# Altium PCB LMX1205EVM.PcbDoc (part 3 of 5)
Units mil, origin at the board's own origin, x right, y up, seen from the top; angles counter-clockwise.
Board outline 5000 x 5000 mil, 6 copper layers (Top Layer, RF GND, Signal Layer 3, Signal Layer 4, Signal Layer 5, Bottom Layer), stack 61.6 mil thick; 176 components, 99 nets, 572 pads, 2473 vias.
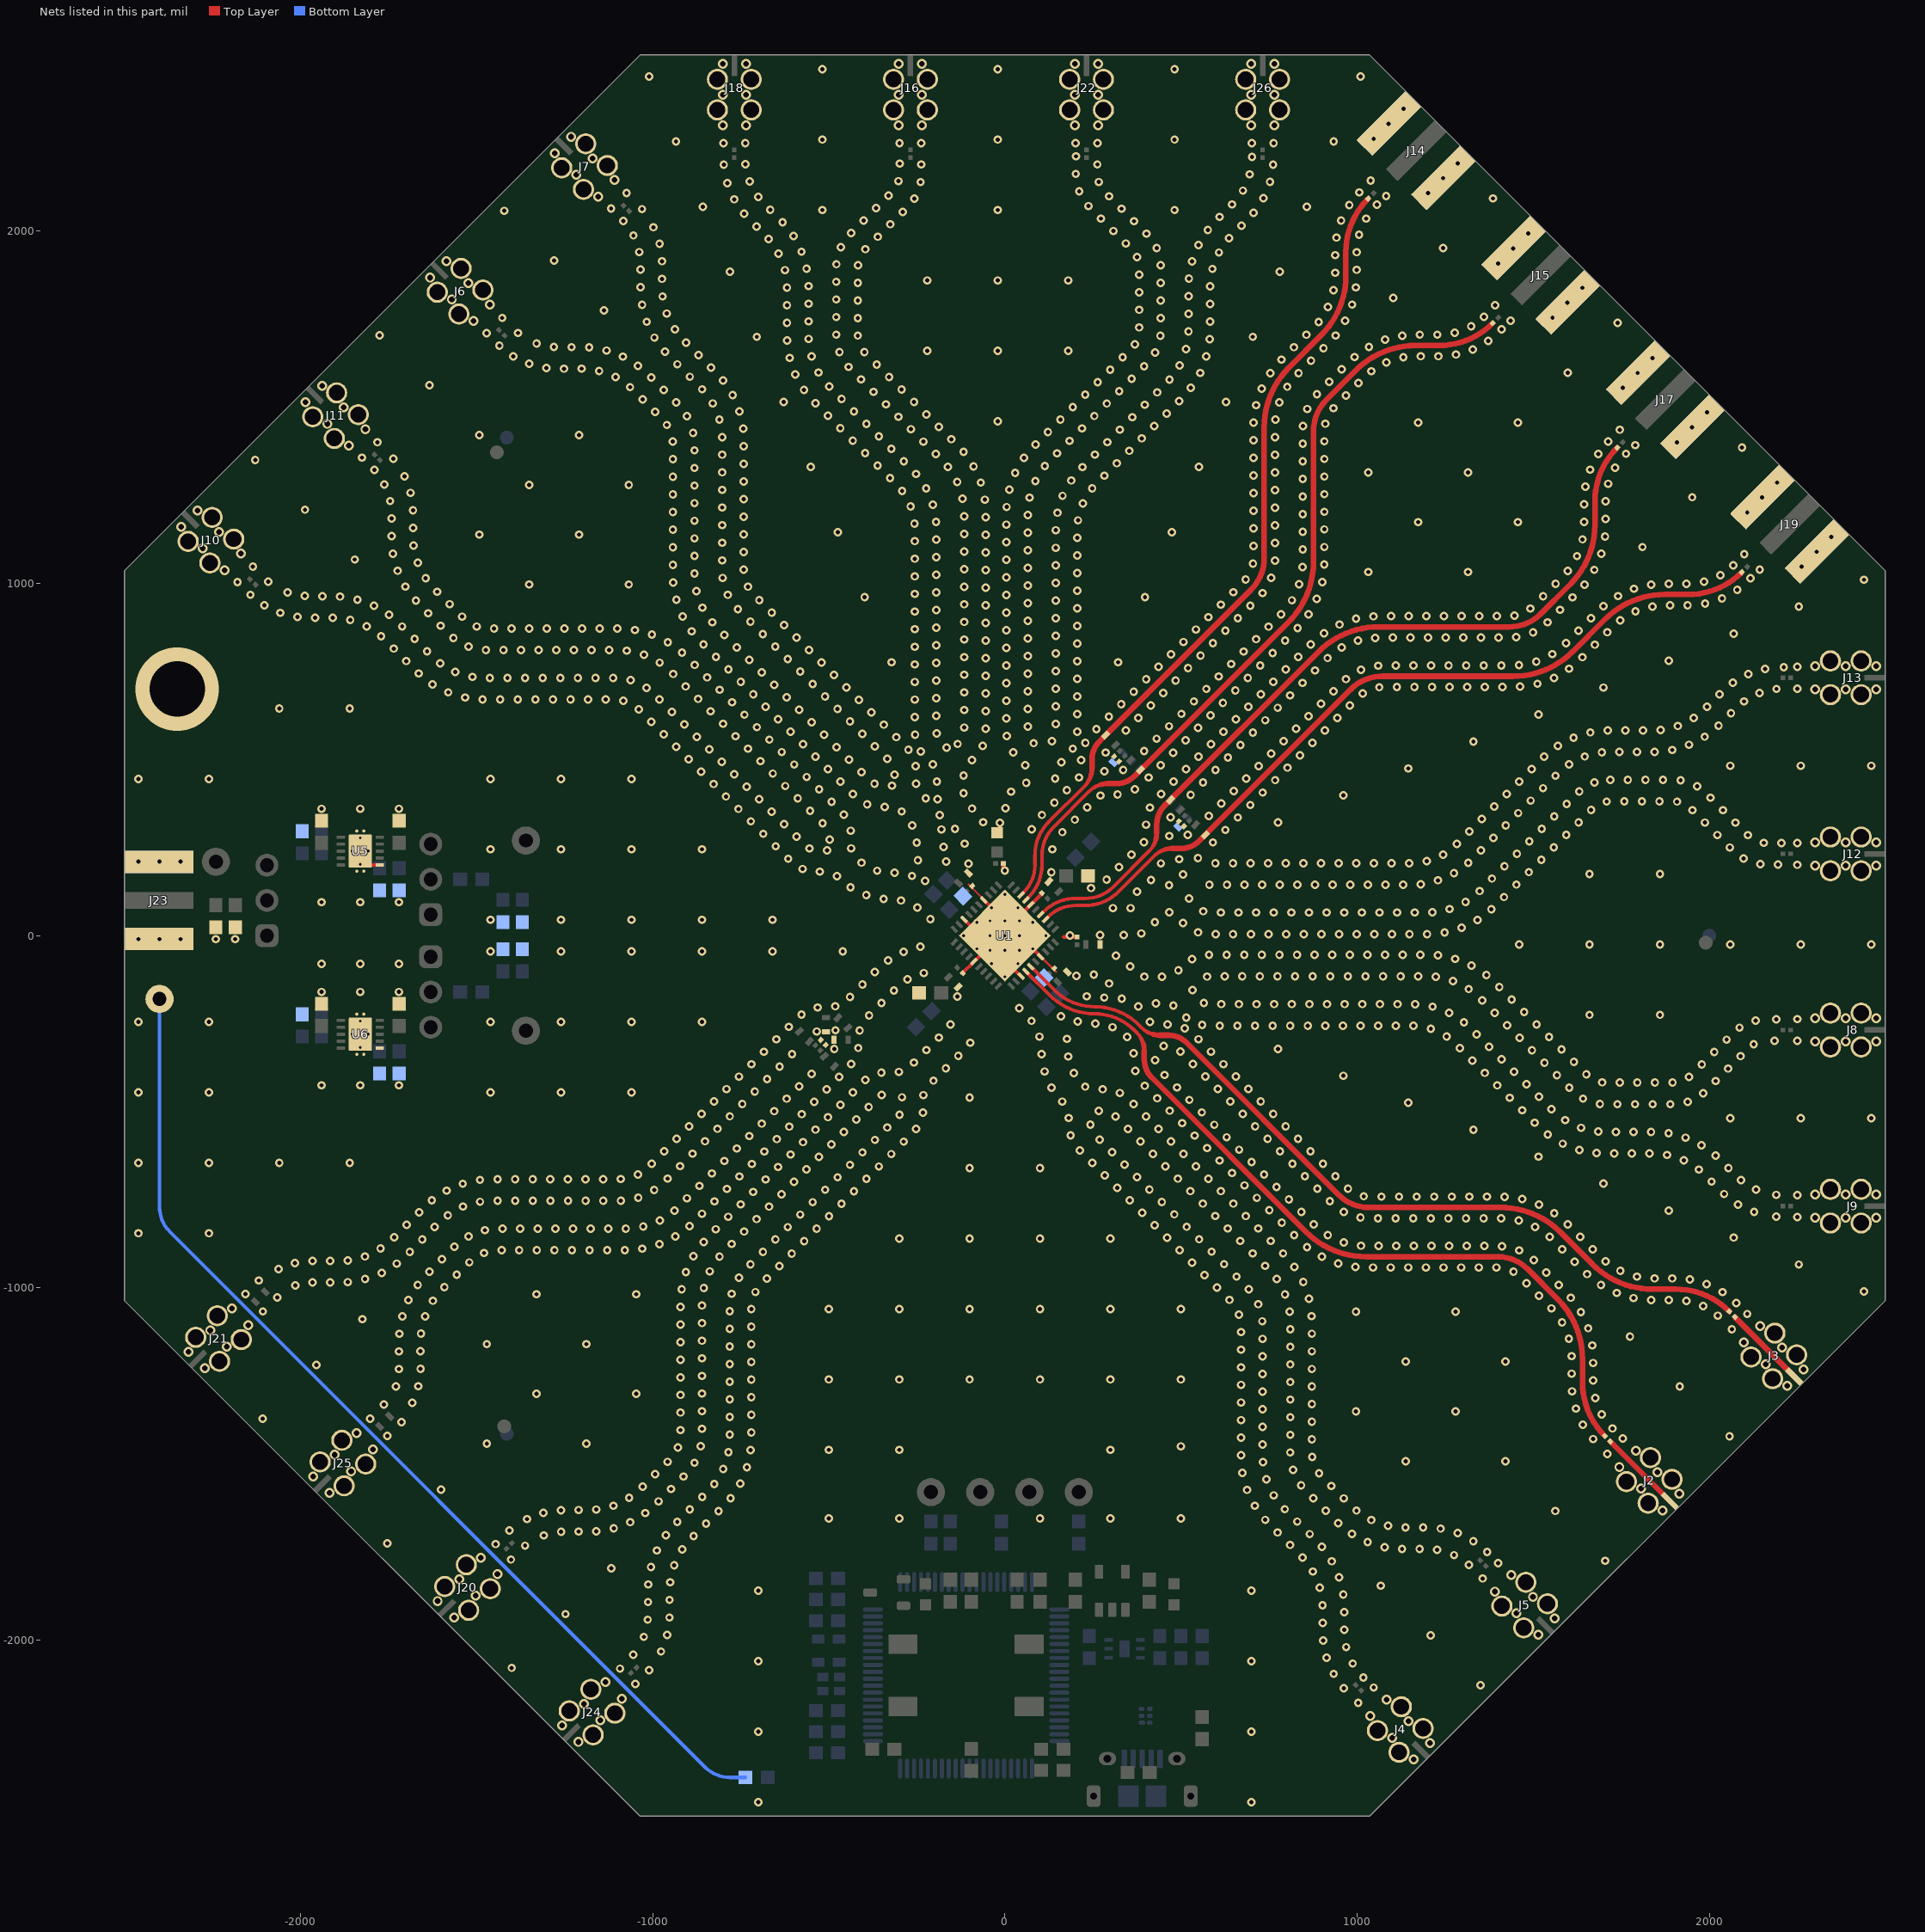
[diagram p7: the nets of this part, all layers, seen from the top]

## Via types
v1: diameter 24, hole 12, Top Layer to Bottom Layer, tented both sides, 2320 vias
v2: diameter 28, hole 16, Top Layer to Bottom Layer, 120 vias
v3: diameter 19.68, hole 7.87, Top Layer to Bottom Layer, tented both sides, 29 vias
v4: diameter 24, hole 12, Top Layer to Bottom Layer, tented bottom, 3 vias
v5: diameter 236.22, hole 157.48, Top Layer to Bottom Layer, tented both sides, 1 vias

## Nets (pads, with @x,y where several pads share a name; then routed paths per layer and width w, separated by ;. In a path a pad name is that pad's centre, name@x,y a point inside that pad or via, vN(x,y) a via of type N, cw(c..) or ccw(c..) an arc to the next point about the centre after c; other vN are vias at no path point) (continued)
GND: C3.2 C4.2 C5.2 C6.2 C8.2 C9.2 C10.2 C11.2 C12.2 C13.2 C14.2 C15.2 C16.1 C21.1 C35.2 C36.2 C51.2 C52.2 C53.1 C54.2 C55.2 C56.2 C57.1 C58.1 C59.2 C60.2 C61.2 C62.1 C63.2 C64.2 C65.1 C66.1 C68.1 C69.1 C70.1 C71.1 J2.2 J2.3 J2.4 J2.5 J3.2 J3.3 J3.4 J3.5 J4.2 J4.3 J4.4 J4.5 J5.2 J5.3 J5.4 J5.5 J6.2 J6.3 J6.4 J6.5 J7.2 J7.3 J7.4 J7.5 J8.2 J8.3 J8.4 J8.5 J9.2 J9.3 J9.4 J9.5 J10.2 J10.3 J10.4 J10.5 J11.2 J11.3 J11.4 J11.5 J12.2 J12.3 J12.4 J12.5 J13.2 J13.3 J13.4 J13.5 J14.2 J14.3 J14.4 J14.5 J15.2 J15.3 J15.4 J15.5 J16.2 J16.3 J16.4 J16.5 J17.2 J17.3 J17.4 J17.5 J18.2 J18.3 J18.4 J18.5 J19.2 J19.3 J19.4 J19.5 J20.2 J20.3 J20.4 J20.5 J21.2 J21.3 J21.4 J21.5 J22.2 J22.3 J22.4 J22.5 J23.2 J23.3 J23.4 J23.5 J24.2 J24.3 J24.4 J24.5 J25.2 J25.3 J25.4 J25.5 J26.2 J26.3 J26.4 J26.5 R5.1 R11.1 R24.2 R28.1 R40.1 R43.1 R44.1 TP3.1 U1.5 U1.13 U1.17 U1.26 U1.34 U1.38 U1.41 U5.6 U5.11 U6.6 U6.11 | length 4042.9
  Top Layer w6: -102.53,144.96 U1.34@-62.23,104.65 ; U1.17@104.65,-62.23 144.96,-102.53
  Top Layer w9.45: U5.11@-1830,200.63 U5.6@-1774.88,200.63
  Top Layer w9.84: U1.38@-115.53,45.93 U1.41@-69.6,0 ; U1.34@-59.85,101.61 v3(-37.58,79.34) ; U1.41@-41.76,-27.84 v3(-41.76,0)
  Top Layer w10: U5.11@-1830,200.63 U5.11@-1830,240 ; C10.2@-120.1,-106.18 U1.5@-87.69,-73.77 U1.41@-41.76,-27.84 ; U1.41@-69.6,0 v3(-41.76,0) v3(0,0) ; v3(-37.58,79.34) v3(0,41.76) U1.41@0,13.92 ; C4.2@-22,292.56 -14,300.56 v1(-14,320) ; U1.13@45.93,-115.53 0,-69.6 v3(0,-41.76) v3(0,0) ; U1.17@101.61,-59.85 v3(79.34,-37.58) v3(41.76,0) v3(0,0) ; C8.2@106.18,120.1 U1.26@73.77,87.69 U1.41@0,13.92 ; v3(0,0) U1.41@0,13.92
  Top Layer w12: v1@-3.98,190 C3.2@-3.98,205 ; 167.42,-3.98 C5.2@205,-3.98
  Bottom Layer w10: TP3.1@-2400,-180 -2400,-770.26 ccw(c-2300,-770.26) -2370.71,-840.97 -850.97,-2360.71 ccw(c-780.26,-2290) -780.26,-2390 R24.2@-736.5,-2390
  other v1: -700,-2460 700,-2460 -700,-2260 700,-2260 1003.38,-2178.6 962.81,-2136.42 1047.23,-2134.76 1350.57,-2128.39 -1048.64,-2124.86 1017.96,-2106.24 933.65,-2095.81 -1010,-2085.26 -1092.48,-2081.02 -1400.07,-2078.89 987.62,-2066.5 -700,-2060 700,-2060 913.99,-2049.83 -1055,-2041.7 -976.26,-2032.34 969.12,-2020.05 903.66,-2000.91 -1025.06,-1990.82 1209.15,-1986.97 -959.01,-1985.41 963.55,-1970.36 902.38,-1950.93 -1014.04,-1942.05 -952.14,-1935.88 -1247.34,-1926.16 963.55,-1920.36 901.94,-1900.93 -1013.05,-1892.06 -951.87,-1885.89 960.69,-1870.44 -700,-1860 700,-1860 894.18,-1851.54 1067.73,-1845.55 -1012.33,-1842.06 -950.42,-1835.91 1356.94,-1825.04 949.21,-1821.77 874.89,-1805.41 -1117.23,-1796.05 -1004.58,-1792.67 -938.68,-1787.31 1317.36,-1786.07 1400.78,-1781.2 928.49,-1776.27 1704.13,-1774.84 -1402.19,-1771.3 844.93,-1765.38 1275.4,-1758.88 1369.55,-1750.22 -987.89,-1745.54 1227.65,-1744.04 -915.83,-1742.83 1127.72,-1741.43 1177.72,-1741.37 1078.01,-1736.02 900.09,-1735.12 -1362,-1732 809.76,-1729.83 -1446.03,-1727.46 -1753.62,-1725.34 1030.15,-1721.57 1330.28,-1719.27 -883.56,-1704.64 -1308.69,-1702.76 -962.49,-1702.47 865.48,-1699.03 985.57,-1698.92 1285.77,-1696.48 774.41,-1694.48 -1259.73,-1692.63 -1209.73,-1691.87 -1159.74,-1690.96 -1406.44,-1689 1237.5,-1683.44 -1110.47,-1682.43 1137.61,-1680.19 1187.61,-1680.19 1087.85,-1675.29 -848.21,-1669.28 946.25,-1668.03 -1063.55,-1665.16 -929.95,-1664.51 830.12,-1663.68 739.46,-1658.72 1040.54,-1659.1 -1356.45,-1656.53 -500,-1655 -300,-1655 100,-1655 300,-1655 500,-1655 -1309.79,-1638.57 -1020.77,-1639.28 -812.85,-1633.93 910.75,-1632.83 1562.71,-1633.42 998.38,-1632.23 -1260.34,-1631.18 -1210.34,-1630.7 -1160.36,-1629.46 -894.59,-1629.15 794.77,-1628.32 -1111.56,-1618.54 709.55,-1618.65 -983.2,-1606.29 962.18,-1597.74 -778.7,-1597.41 875.39,-1597.47 -1066.71,-1596.45 -859.24,-1593.8 763.61,-1589.22 687.76,-1573.65 -1600.89,-1572.61 -947.84,-1570.93 -1028.11,-1564.68 926.82,-1562.39 841.15,-1561.04 -825.04,-1557.32 -751.48,-1555.47 742.48,-1543.9 -912.49,-1535.57 -992.75,-1529.32 892.15,-1526.36 674.71,-1525.38 818.26,-1516.59 -799.53,-1514.32 -732.26,-1509.31 -881.09,-1496.66 732.6,-1494.89 -957.39,-1493.96 1138.44,-1492 1421.28,-1492 872.68,-1480.31 670.45,-1475.56 1710.49,-1471.49 -784.85,-1466.52 810.26,-1467.23 -721.6,-1460.46 -500,-1460 -300,-1460 300,-1460 -928.15,-1453.41 -863.23,-1449.96 500,-1450 731.63,-1444.9 -1470.78,-1442.5 -1187.94,-1442.5 871.63,-1430.32 1669.91,-1429.32 1754.33,-1427.65 670.45,-1425.56 -1752.92,-1420.58 2057.68,-1421.28 -781.13,-1416.66 810.45,-1417.23 -719.95,-1410.48 -921.13,-1403.91 -859.95,-1400.07 1725.06,-1399.14 731.63,-1394.9 1640.76,-1388.7 -1713,-1381 871.63,-1380.32 670.45,-1375.56 -2107.18,-1371.79 -1802.42,-1371.08 -781.13,-1366.66 810.45,-1367.23 -719.95,-1360.48 1694.72,-1359.4 -921.13,-1353.91 997.02,-1350.57 1279.86,-1350.57 -859.95,-1350.07 731.63,-1344.9 1621.1,-1342.72 -1763,-1331 871.63,-1330.32 -1682.1,-1326.43 670.45,-1325.56 -781.13,-1316.66 810.45,-1317.23 1676.23,-1312.94 -719.95,-1310.48 -921.13,-1303.91 -1329.36,-1301.08 -1046.52,-1301.08 -859.95,-1300.07 731.63,-1294.9 1610.77,-1293.8 -1729.04,-1279.68 871.63,-1280.32 1916.26,-1279.86 -1665.04,-1279.43 670.45,-1275.56 -781.13,-1266.66 810.45,-1267.23 1670.66,-1263.25 -719.95,-1260.48 -500,-1260 -300,-1260 -100,-1260 100,-1260 300,-1260 500,-1260 -921.13,-1253.91 -859.95,-1250.07 731.63,-1244.9 1609.48,-1243.82 -1720.33,-1230.45 -1658.79,-1229.82 871.63,-1230.32 670.45,-1225.56 -1954.44,-1219.05 -781.13,-1216.66 810.45,-1217.23 1670.66,-1213.25 -719.95,-1210.48 1138.44,-1209.15 1421.28,-1209.15 -921.13,-1203.91 -859.95,-1200.07 731.63,-1194.9 1609.05,-1193.82 -1720.16,-1180.45 -1658.98,-1179.82 871.63,-1180.32 670.45,-1175.56 -781.13,-1166.66 810.45,-1167.23 1667.79,-1163.34 -1470.78,-1159.66 -1187.94,-1159.66 -719.95,-1160.48 -921.13,-1153.91 -859.95,-1150.07 731.63,-1144.9 1601.29,-1144.43 1774.84,-1138.44 -1719.18,-1130.46 -1657.6,-1129.84 871.63,-1130.32 670.45,-1125.56 2064.04,-1117.94 -781.13,-1116.66 810.45,-1117.23 1656.32,-1114.67 -719.95,-1110.48 -921.13,-1103.91 -859.95,-1100.07 1582,-1098.3 730.96,-1094.9 -1824.34,-1088.94 -1710.44,-1081.23 -1646.11,-1081.17 871.02,-1080.32 2024.49,-1078.98 664.96,-1075.87 2107.89,-1074.1 1635.6,-1069.17 997.02,-1067.73 1279.86,-1067.73 -2106.47,-1067.02 -781.13,-1066.66 808.49,-1067.27 -719.95,-1060.48 -500,-1060 -300,-1060 -100,-1060 100,-1060 300,-1060 500,-1060 1552.03,-1058.27 -921.13,-1053.91 1982.53,-1051.79 -859.95,-1050.07 719.14,-1046.32 2076.62,-1043.08 -1623.5,-1036.58 1934.79,-1036.94 -1693.11,-1034.33 637.36,-1034.17 1834.86,-1034.33 1884.86,-1034.26 863.7,-1030.86 1785.15,-1028.92 1607.2,-1028.01 -2066,-1027 1516.87,-1022.73 795.66,-1018.94 -2155.97,-1017.53 -1329.36,-1018.23 -1046.52,-1018.23 -775.58,-1016.97 1737.29,-1014.47 -708.05,-1011.92 2037.34,-1012.13 2439.04,-1010.28 -917.63,-1004.03 692.76,-1003.84 -854.52,-1000.37 602.01,-998.82 -1591.39,-998.25 -2014.65,-993.51 -1667,-991.69 1572.59,-991.93 1692.71,-991.83 1992.83,-989.36 1481.51,-987.37 -1965.4,-984.91 -1915.4,-984.77 -1865.41,-983.77 847.21,-983.66 -2118,-979 1944.56,-976.32 -1816.19,-974.93 771.68,-975.07 -675.85,-973.67 1844.67,-973.09 1894.67,-973.09 -755.15,-971.33 657.8,-968.1 1794.91,-968.17 -1556.04,-962.9 566.65,-963.46 1653.38,-960.95 -1769.3,-957.58 1537.23,-956.57 -905.55,-955.51 -1633.88,-954.23 1444.01,-954.3 -837.67,-953.29 1747.61,-951.97 -2062.23,-946.91 1045.46,-942.34 1095.46,-942.34 1145.46,-942.34 1195.46,-942.34 1245.46,-942.34 1295.46,-942.34 1345.46,-942.34 1395.46,-942.34 995.49,-940.78 822.19,-940.37 -640.5,-938.31 738.68,-937.5 -722.32,-933.62 2254.27,-933.75 622.45,-932.74 -1726.73,-931.36 -2015.27,-929.74 946.56,-930.49 -1520.6,-927.62 531.3,-928.11 1617.88,-925.74 1705.45,-925.09 -1915.67,-923.59 -1965.67,-923.43 -1865.69,-922.23 1501.85,-921.24 -1598.53,-918.87 -810.21,-911.51 900.26,-911.62 -1817,-910.87 -884.23,-910.28 -605.14,-902.96 703.33,-902.15 789.89,-902.2 -1478.27,-901.01 -1689.32,-898.19 -686.96,-898.26 587.09,-897.39 1460.11,-893.73 -1428.94,-892.84 -1378.94,-892.84 -1328.94,-892.84 -1278.94,-892.84 -1228.94,-892.84 -1178.94,-892.84 -1128.94,-892.84 -1078.94,-892.84 495.94,-892.75 1669.25,-890.6 1582.52,-890.39 -1029.11,-888.8 -1772.35,-888.36 858.12,-884.71 -1563.2,-883.49 1411.57,-881.7 1061.58,-881.16 1111.58,-881.16 1161.58,-881.16 1211.58,-881.16 1261.58,-881.16 1311.58,-881.16 1361.58,-881.16 1011.58,-880.37 -980.77,-876.02 -775.6,-875.43 962.43,-871.19 -855.14,-869.62 -569.79,-867.6 667.97,-866.79 754.54,-866.84 -1653.96,-862.83 -651.61,-862.91 551.74,-862.03 -300,-860 -100,-860 100,-860 300,-860 460.58,-857.4 2069.49,-857.21 -1733.96,-856.32 1546.68,-855.53 1633.89,-855.24 -1522.84,-853.98 -935.7,-854.36 821.52,-850.64 916.82,-850.71 -2460,-845 -2260,-845 -740.24,-840.07 -1476.03,-836.38 -820.37,-833.68 -1426.26,-831.67 -1376.26,-831.67 -1326.26,-831.67 -1276.26,-831.67 -1226.26,-831.67 -1176.26,-831.67 -1126.26,-831.67 -1076.26,-831.67 -534.43,-832.25 632.62,-831.44 719.18,-831.49 -616.25,-827.55 -1618.6,-827.48 516.38,-826.68 1505.66,-826.94 -1026.6,-825.83 -895.47,-824.67 425.23,-822.04 -1698.61,-820.97 877.35,-820.01 1598.63,-819.8 786.17,-815.28 1459.07,-808.8 -979.71,-808.47 -704.89,-804.71 1059.49,-802.34 1109.49,-802.34 1159.49,-802.34 1209.49,-802.34 1259.49,-802.34 1309.49,-802.34 1359.49,-802.34 1409.49,-802.35 1009.52,-800.46 2250,-799 -785.02,-798.33 2190,-797.5 -499.08,-796.89 597.26,-796.08 683.83,-796.13 -1581.57,-793.89 -580.9,-792.2 481.02,-791.32 -859.66,-789.78 1559.92,-788.15 389.87,-786.68 -1663.25,-785.61 842.03,-784.63 962.12,-784.54 2127.35,-784.75 -938.23,-780.56 1884.71,-780.67 750.81,-779.93 -1538.17,-769.06 -669.53,-769.36 1516.16,-763.95 2081.98,-763.74 -749.66,-762.97 -463.72,-761.54 561.91,-760.73 648.47,-760.78 -545.54,-756.84 -1490.01,-755.61 445.67,-755.97 -824.3,-754.42 922.68,-753.81 -1440.09,-752.84 -1390.09,-752.84 -1340.09,-752.84 -1290.09,-752.84 -1240.09,-752.84 -1190.09,-752.84 -1140.09,-752.84 -1090.09,-752.58 -1626.92,-751.26 354.52,-751.33 806.67,-749.27 1468.78,-748 -902.24,-745.84 715.46,-744.57 -1040.86,-743.8 1419.2,-741.54 1069.2,-741.16 1119.2,-741.16 1169.2,-741.16 1219.2,-741.16 1269.2,-741.16 1319.2,-741.16 1369.2,-741.16 1019.21,-740.02 2250,-737 2190,-736 -634.18,-734 2042.1,-733.58 -714.31,-727.62 -428.37,-726.18 526.55,-725.37 613.12,-725.42 -1585.06,-723.92 -995.76,-722.21 -510.19,-721.49 410.31,-720.61 2132.61,-720.93 -788.95,-719.07 887.33,-718.45 974.21,-718.24 319.16,-715.97 771.32,-713.92 -866.88,-710.49 680.1,-709.22 -1539.03,-704.39 1699.94,-704.14 -598.82,-698.65 2006.56,-698.41 -1490.22,-693.55 2090.32,-694.25 -1440.25,-691.67 -1390.25,-691.67 -1340.25,-691.67 -1290.25,-691.67 -1240.25,-691.67 -1190.25,-691.67 -1140.25,-691.67 -678.95,-692.26 -1090.26,-691.12 -393.01,-690.83 -957.68,-689.81 491.2,-690.02 577.76,-690.07 -474.83,-686.13 374.96,-685.25 -753.59,-683.71 851.97,-683.1 938.56,-683.17 283.81,-680.62 735.96,-678.56 -1041.89,-678.45 -831.53,-675.13 644.75,-673.86 1970.19,-664.1 -563.47,-663.29 -100,-660 100,-660 2054.27,-659.6 -643.6,-656.91 -357.65,-655.47 455.84,-654.66 542.41,-654.71 -922.33,-654.46 -439.48,-650.78 339.6,-649.9 -1002.3,-647.91 -718.24,-648.36 816.62,-647.74 903.21,-647.82 -2460,-645 -2260,-645 -2060,-645 -1860,-645 248.45,-645.26 700.61,-643.21 -796.17,-639.78 609.39,-638.51 1927.51,-638.05 -528.11,-627.94 1515.16,-627.6 2018.41,-624.76 1879.9,-622.77 -608.24,-621.55 -322.3,-620.12 -886.97,-619.1 420.49,-619.31 507.05,-619.36 1730.08,-618.59 1780.08,-618.59 1830.08,-618.59 1680.09,-617.52 -404.12,-615.42 304.25,-614.54 -966.94,-612.56 -682.88,-613 781.26,-612.39 867.85,-612.46 213.1,-609.91 665.25,-607.85 1630.93,-608.43 -760.82,-604.42 574.04,-603.15 1978.02,-595.29 -492.76,-592.58 1584.13,-590.83 -572.88,-586.2 -286.94,-584.76 -851.62,-583.75 385.13,-583.95 471.69,-584 -368.77,-580.07 268.89,-579.19 -647.53,-577.65 -931.59,-577.2 745.91,-577.03 832.5,-577.11 1932.89,-573.76 629.9,-572.5 -725.46,-569.07 538.68,-567.8 186.71,-567.44 1541.62,-564.49 1884.48,-561.25 -457.4,-557.23 1734.63,-557.41 1784.63,-557.41 1834.63,-557.41 1684.64,-556.26 -537.53,-550.84 1330.39,-551.06 -252.3,-548.71 349.77,-548.6 436.34,-548.65 -816.26,-548.39 1635.77,-545.68 -333.41,-544.71 -896.23,-541.85 -612.17,-542.29 710.55,-541.68 797.14,-541.75 594.54,-537.14 242.94,-536.45 -690.11,-533.71 503.33,-532.44 1504.34,-531.18 1590.77,-523.9 -422.05,-521.87 181.54,-517.71 2060,-518 2260,-518 2460,-518 -502.17,-515.48 -780.91,-513.04 314.42,-513.24 400.98,-513.29 -298.93,-508.5 -576.82,-506.94 -860.88,-506.49 675.2,-506.32 761.79,-506.4 -232.34,-502.86 559.18,-501.78 -654.75,-498.36 267.04,-497.28 467.97,-497.09 1468.98,-495.82 1552,-492.32 -386.69,-486.52 -466.82,-480.13 1739.33,-478.59 1789.33,-478.59 1839.33,-478.59 1889.33,-478.59 -745.55,-477.68 365.63,-477.93 1689.34,-477.69 1145.61,-474.53 -541.46,-471.58 1938.91,-472.1 -825.52,-471.14 163.21,-471.19 639.84,-470.97 726.43,-471.04 523.83,-466.43 -619.4,-463 1641.6,-462.84 432.61,-461.73 -100,-460 1433.63,-460.47 -291.79,-459.01 1516.65,-456.97 -349.77,-452.8 -231.05,-452.88 1982.59,-447.77 326.54,-446.76 -2460,-445 -2260,-445 -1460,-445 -1260,-445 -1060,-445 -431.46,-444.77 -710.19,-442.33 -790.17,-435.78 -506.11,-436.23 277.69,-436.1 604.48,-435.61 691.08,-435.69 132.69,-431.59 488.47,-431.07 1602.65,-431.49 228.22,-428.8 -584.04,-427.65 397.26,-426.38 -1940,-425 -1830,-425 -1720,-425 1398.27,-425.11 1481.29,-421.61 1695.61,-416.59 1745.61,-417.41 1795.61,-417.41 1845.61,-417.41 1895.61,-417.41 2018.39,-412.86 -202.65,-411.73 -395.63,-409.91 -674.84,-406.97 -470.75,-400.87 1942.85,-401.02 -754.81,-400.43 569.13,-400.26 655.72,-400.33 960.83,-397.99 453.12,-395.72 1567.29,-396.14 1651.23,-393.57 -548.69,-392.29 196.16,-390.43 1362.92,-389.76 -350.4,-388.58 -300.43,-386.94 112.62,-385.79 1445.94,-386.26 370.68,-384.02 2053.75,-377.51 -167.29,-376.37 -639.48,-371.61 1978.64,-366.11 -719.46,-365.07 -436.11,-364.81 533.77,-364.9 620.36,-364.98 1531.94,-360.78 -258.17,-360.22 1615.88,-358.21 1327.56,-354.4 426.84,-353.18 1410.58,-350.9 180.05,-343.1 2089.1,-342.15 -131.94,-341.02 103.99,-336.54 -604.13,-336.26 365.39,-334.3 2013.99,-330.75 -684.1,-329.72 498.42,-329.54 585.01,-329.62 -222.82,-324.86 1496.58,-325.43 1580.52,-322.85 -484.37,-321.73 776.06,-321.45 -416.19,-318.96 1292.21,-319.04 1375.22,-315.55 451.09,-313.43 2126.13,-308.55 -98.24,-304.07 2185,-298.59 2250,-299 2049.35,-295.4 -648.74,-294.36 549.65,-294.26 176.35,-293.24 -187.46,-289.51 1461.22,-290.07 347.49,-287.62 97.92,-286.91 1545.17,-287.5 1254.53,-286.18 1339.87,-280.19 -533.87,-272.24 -480.83,-268.7 -412.35,-269.1 1209.6,-264.24 510.61,-263.03 2085.93,-261.32 305.75,-260.09 -613.39,-259 610.31,-255.59 660.31,-255.59 710.31,-255.59 760.31,-255.59 810.31,-255.59 860.31,-255.59 910.31,-255.59 960.31,-255.59 1010.31,-255.59 1060.31,-255.59 1110.31,-255.59 1160.31,-255.82 1425.87,-254.72 560.35,-253.65 -154.16,-252.2 461.78,-252.26 1509.81,-252.14 256.88,-249.54 1303.55,-245.83 -2460,-245 -2260,-245 -1460,-245 -1260,-245 -1060,-245 -860,-245 412.29,-245.14 207.19,-243.91 75.75,-242.1 2131.63,-241.02 2190,-237.41 2250,-237 515.1,-232.37 159,-229 -385.52,-226.91 1660,-225 1860,-225 -577.37,-224.33 1261.24,-219.19 1390.51,-219.36 1474.46,-216.79 41.25,-205.9 -531.64,-204.11 1214.46,-201.52 -481.76,-200.57 379,-201 478.55,-198.25 1164.94,-194.63 614.94,-194.41 664.94,-194.41 714.94,-194.41 764.94,-194.41 814.94,-194.41 864.94,-194.41 914.94,-194.41 964.94,-194.41 1014.94,-194.41 1064.94,-194.41 1114.94,-194.41 428.85,-192.84 -350.17,-191.55 565.03,-191.4 1355.16,-184 1439.1,-181.43 332,-179 282.12,-176.03 -439.5,-173.85 -135,-173 232.26,-172.33 -1940,-160 -1830,-160 -1720,-160 -314.81,-156.2 533,-155 1316.98,-151.72 1403.75,-146.08 -404.15,-138.5 296.03,-135.87 1272.52,-128.83 -276.26,-124.36 446.47,-117.16 1223.93,-117.05 396.48,-116.31 573.96,-116.33 623.95,-115.59 673.95,-115.59 723.95,-115.59 773.95,-115.59 823.95,-115.59 873.95,-115.59 923.95,-115.59 973.95,-115.59 1023.95,-115.59 1073.95,-115.59 1123.95,-115.59 1173.95,-115.59 203,-114 1367.15,-112.01 252.73,-110.87 -229.64,-106.27 -368.79,-103.14 492.97,-98.77 355.47,-87.7 1325.01,-85.1 -1940,-80 -1830,-80 -1720,-80 -330.95,-70.46 531.4,-66.78 1278.7,-66.24 315.82,-57.25 1229.77,-55.96 579.79,-54.22 629.79,-54.41 679.79,-54.41 729.79,-54.41 779.79,-54.41 829.79,-54.41 879.79,-54.41 929.79,-54.41 979.79,-54.41 1029.79,-54.41 1079.79,-54.41 1129.79,-54.41 1179.79,-54.41 -287.42,-45.86 -1460,-45 -1260,-45 -1060,-45 -860,-45 -660,-45 -460,-45 -239.46,-31.72 1460,-25 1660,-25 1860,-25 2060,-25 2260,-25 2460,-25 -2460,-10 -2400,-10 -2340,-10 -2240,-10 -2185,-10 185,0 270,1.82 337.9,1.82 598.73,4.41 648,4.41 698.73,4.41 748.73,4.41 798.73,4.41 848.73,4.41 898.73,4.41 948.73,4.41 998.73,4.41 1048.73,4.41 1098.73,4.41 1148.73,4.41 1198.73,4.41 387.73,6 548.97,9.35 1248.52,8.94 1296.69,22.34 506.31,35.43 426.05,38.11 1341.62,44.28 -1460,45 -1260,45 -1060,45 -860,45 -660,45 -211.3,46.65 613.45,65.59 663.45,65.59 713.45,65.59 763.45,65.59 813.45,65.59 863.45,65.59 913.45,65.59 963.45,65.59 1013.45,65.59 1063.45,65.59 1113.45,65.59 1163.45,65.59 1213.44,66.36 467.17,66.55 563.57,69.16 1381.47,74.49 1262.6,75.47 307,78 357,78 -248.49,80.06 -1940,95 -1830,95 -1720,95 1308.25,95.88 -294.46,99.73 -344.23,104.49 523,105 1417.16,109.49 -393.1,115.1 375,125 1347.77,126.51 245.08,135.06 -438.04,137 466.29,143.33 580.86,144.35 630.86,144.41 680.86,144.41 730.86,144.41 780.86,144.41 830.86,144.41 880.86,144.41 930.86,144.41 980.86,144.41 1030.86,144.41 1080.86,144.41 1130.86,144.41 1452.52,144.85 1180.84,145.91 -226,155 1229.59,157.02 415,158 289.1,158.77 1383.07,161.92 -476.74,168.66 -263.53,169.52 505.76,174.02 1660,175 1860,175 1275.3,177.28 -312.78,178.2 132,180 1487.87,180.21 -525.05,181.54 -362.41,184.22 0,185 -574.47,189.15 324.46,194.13 1418.43,197.27 2194.77,201.41 2250,201 2144.79,202.64 -103,204 443,205 597.96,205.59 647.96,205.59 697.96,205.59 747.96,205.59 797.96,205.59 847.96,205.59 897.96,205.59 947.96,205.59 997.96,205.59 1047.96,205.59 1097.96,205.59 1147.96,205.59 -406.86,207.13 1315.67,206.77 -2460,210 -2400,210 -2340,210 -166.25,210.11 1197.63,211.32 -246.64,214.35 1523.23,215.56 495,217.06 -615.1,218.29 2097.43,218.69 548.23,220 359.81,229.48 1244.02,229.96 1453.78,232.63 -504.73,241.95 1351.42,241.74 -1460,245 -1260,245 -1060,245 -860,245 135,245 -554.42,247.52 -436.07,247.7 2058.58,250.16 1558.58,250.92 -173.99,251.71 -650.46,253.65 1283.64,260.47 -114.03,260.9 2154.77,263.45 2204.76,262.59 2250,263 -250.12,264.23 394.79,265.21 590.78,264.68 1489.14,267.98 -497.28,272.85 1386.77,277.09 -591.43,281.14 466.69,282.84 2109.85,285.41 519.72,286.38 1593.94,286.27 2023.23,285.51 -685.81,289 163.45,293.78 1318.99,295.83 -437.39,297.69 626.13,300.03 -179.66,301.39 76.2,302.15 -141.53,302.66 1524.49,303.34 1422.13,312.45 -262.91,312.56 400.75,314.86 -626.79,316.49 -517.43,318.61 776.06,321.45 1987.87,320.87 2074.49,320.77 -61.38,322.01 1629.3,321.63 -721.17,324.36 198.81,329.13 1354.35,331.18 661.49,335.39 470.23,335.88 1559.85,338.69 579.37,339.78 -185,342 105.2,342.56 -457.29,343.56 1457.48,347.8 -662.14,351.85 -292.93,352.55 -552.79,353.96 1952.52,356.23 2039.14,356.12 1664.65,356.98 -1940,360 -1830,360 -1720,360 -756.52,359.71 -92.88,360.84 1.82,361.34 234.16,364.49 412.27,363.51 -341.25,365.39 1389.7,366.54 696.85,370.74 -390.67,373.02 1595.2,374.05 614.72,375.14 140.55,377.92 -491.92,379.62 1908.75,380.4 1708.77,380.51 1758.76,381.41 1808.76,381.41 1858.76,381.41 1492.84,383.16 -697.5,387.2 -191.16,387.65 -588.14,389.32 -224.63,389.9 2003.78,391.48 -791.88,395.07 271.67,397.56 960.83,397.99 527.4,399.29 320,400.91 -431.29,402.17 443.86,402.27 1425.06,401.89 -117.11,404.58 732.2,406.1 17.75,408.74 1630.78,409.18 650.08,410.49 175.91,413.27 -527.28,414.97 369.4,415.42 1528.19,418.51 -732.85,422.56 1965.68,423.85 -623.5,424.68 -320.23,425.66 -827.23,430.42 -369.94,431.03 -252.24,431.59 60.9,434.01 562.75,434.64 1673.67,434.88 1460.41,437.25 -466.65,437.53 -192.84,437.62 479.22,437.62 767.56,441.46 1918.7,440.96 1718.72,442.59 1768.72,442.59 1818.72,442.59 1868.72,442.59 -2460,445 -2260,445 -1460,445 -1260,445 -1060,445 142.84,445.69 685.43,445.85 210.89,449 408,449 -562.64,450.33 1563.55,453.87 -117.16,454.58 -313.43,456.54 -768.21,457.91 -658.85,460.03 -407.1,464.5 -862.59,465.78 282.84,466.69 335.88,470.23 598.11,470 -502,472.89 514.57,472.98 1495.77,472.6 1145.61,474.53 802.91,476.81 720.79,481.2 -253.55,481.57 2060,482 2260,482 2460,482 57.92,483.92 442.25,483.85 -597.99,485.68 -204.07,486.34 1601.88,485.97 160.66,492.41 -803.56,493.27 -694.21,495.39 -93.25,498.49 216.9,498.64 -442.45,499.85 -897.94,501.13 -333.48,502.35 633.46,505.35 -537.36,508.24 549.93,508.33 1531.19,507.89 1646.49,508.57 838.27,512.17 756.14,516.56 477.61,519.2 23.47,520.16 286.38,519.72 1695.15,520.03 -633.35,521.04 1745.14,521.41 1795.14,521.41 1845.14,521.43 -238.2,522.88 395.47,523.58 -273.47,527.43 1894.82,527.01 -838.92,528.62 -729.56,530.74 192.84,530.68 -165.08,533.34 -477.81,535.21 -933.3,536.49 -368.83,537.71 -63.06,538.35 1570.37,538.96 668.82,540.71 1942.59,541.78 -572.71,543.6 -134.09,544.17 585.28,543.69 81.83,546.43 228.39,547.3 873.62,547.52 1330.39,551.06 133.34,552.08 791.5,551.91 512.96,554.56 -668.7,556.4 430.83,558.94 1614.74,562.01 -308.1,563.49 -874.28,563.98 1987.02,564.72 -764.92,566.1 5.37,566.77 -254.94,570 -513.16,570.56 -968.66,571.84 -404.19,573.06 -193.71,574.33 704.17,576.06 1662.47,576.9 -608.07,578.95 205.62,579.02 620.64,579.04 343.35,582.93 908.98,582.88 1712.15,582.54 1762.15,582.59 1812.15,582.59 1862.13,583.93 259.97,586.07 826.85,587.27 -54.41,587.59 548.32,589.91 -115.59,590.62 -704.06,591.75 65.59,593.72 466.18,594.29 1910.83,595.26 2026.23,595.74 -909.63,599.33 -343.46,598.85 -800.27,601.45 144.41,600.84 -548.52,605.92 -1004.01,607.2 -439.54,608.42 739.53,611.42 -643.42,614.31 655.99,614.4 4.41,616.76 378.7,618.29 944.33,618.23 1955.5,617.73 -255.59,619.99 295.32,621.42 862.21,622.62 -194.41,624.33 583.67,625.27 -739.41,627.11 1515.16,627.6 205.59,629.02 501.54,629.65 2061.68,631.01 -378.81,634.2 -944.99,634.69 -835.63,636.81 -54.41,637.59 -583.87,641.27 -115.59,640.62 -1039.41,642.51 -474.9,643.77 65.59,643.72 -2060,645 -1860,645 774.88,646.77 -678.78,649.66 691.35,649.75 1993.9,649.75 144.41,650.84 414.06,653.64 979.69,653.59 330.68,656.78 897.57,657.98 619.03,660.63 -774.77,662.46 536.89,665 2098.41,664.93 -1082.96,667.07 4.41,666.76 -1482.85,670.43 -1432.85,670.45 -1382.85,670.45 -1332.85,670.45 -1282.85,670.45 -1232.85,670.45 -1182.85,670.45 -1132.85,670.45 -980.34,670.05 -414.17,669.56 -255.59,669.99 -870.98,672.16 -194.41,674.33 -1532.55,675.93 -619.23,676.63 -510.25,679.13 205.59,679.02 810.24,682.13 -714.13,685.02 726.7,685.11 2029.26,685.1 -54.41,687.59 1016.09,687.86 449.41,689 2142.24,689 -1580.36,690.54 -115.59,690.62 366.03,692.13 932.92,693.34 65.59,693.72 654.39,695.98 -810.12,697.82 572.25,700.36 2190.93,700.34 144.41,700.84 2250,701 -1017.34,703.67 1699.94,704.14 -449.53,704.91 1063.04,705.05 1113.04,705.81 1163.04,705.81 1213.04,705.81 1263.04,705.81 1313.04,705.81 1363.04,705.81 1413.04,705.81 1463.03,706.66 -906.34,707.52 -654.58,711.98 -1624.86,713.34 -545.61,714.48 1512.34,714.92 4.41,716.76 845.6,717.49 2067.09,717.8 -749.49,720.37 -255.59,719.99 762.06,720.46 -194.41,724.33 484.77,724.35 -1062.45,725.25 401.39,727.49 968.67,728.29 205.59,729.02 689.74,731.34 -1462.04,731.63 -1412.04,731.63 -1362.04,731.63 -1312.04,731.63 -1262.04,731.63 -1212.04,731.63 -1162.04,731.63 -1112.04,731.63 1559.39,731.86 -845.48,733.17 -1511.96,734.54 607.6,735.71 -54.41,737.59 -484.88,740.27 -115.59,740.62 2110.57,742.48 -941.69,742.87 -1664.13,744.3 65.59,743.72 -689.94,747.34 -1560.06,748.18 -580.96,749.84 144.41,750.84 880.95,752.84 1011.18,754.62 -784.84,755.73 797.41,755.82 2158.31,757.34 1602.19,757.7 520.12,759.71 2211.58,762.19 436.74,762.84 2250,763 1059.78,766.35 4.41,766.76 725.1,766.69 1109.78,766.98 1159.78,766.98 1209.78,766.98 1259.78,766.98 1309.78,766.98 1359.78,766.98 1409.78,766.98 1459.77,767.97 -880.83,768.53 -255.59,769.99 642.96,771.07 -1603.41,773.1 -194.41,774.33 -980.02,774.98 -520.24,775.63 -321.45,776.06 321.45,776.06 1508.77,777.91 205.59,779.02 -1699.6,779.53 1884.71,780.67 -725.29,782.69 -616.32,785.19 -54.41,787.59 916.48,788.03 -820.2,791.08 -115.59,790.62 832.77,791.17 1639.9,790.54 65.59,793.72 555.48,795.07 -1024.62,797.59 472.1,798.2 1554.06,799.1 144.41,800.84 760.45,802.05 -916.64,803.42 678.31,806.43 -1640.35,806.79 -1073.28,809.07 -1423.26,810.45 -1373.26,810.45 -1323.26,810.45 -1273.26,810.45 -1223.26,810.45 -1173.26,810.45 -1123.26,810.45 -1473.26,810.57 -555.59,810.98 -1734.96,814.89 4.41,816.76 -760.65,818.05 956.42,818.1 -1522.29,820.36 -255.59,819.99 -651.67,820.55 -194.41,824.33 -855.55,826.44 1675.25,825.89 868.13,826.53 205.59,829.02 590.84,830.42 1593.14,830.29 -956.87,833.12 507.45,833.55 795.81,837.4 1002.52,837.45 -54.41,837.59 -115.59,840.62 -1675.7,842.15 713.67,841.78 65.59,843.72 -1565.75,845.1 1051.9,845.34 -590.95,846.34 1101.9,845.81 1151.9,845.81 1201.9,845.81 1251.9,845.81 1301.9,845.81 1351.9,845.81 1401.9,845.81 1451.88,847.03 -1770.84,849.71 144.41,850.84 -796,853.4 -1001.93,854.78 -687.03,855.9 2069.49,857.21 906.49,858.6 1499.87,861.08 1710.61,861.25 -888.76,863.82 626.19,865.78 1628.49,865.65 4.41,866.76 -1050.27,867.57 542.81,868.91 -255.59,869.99 -1450.1,871.63 -1400.1,871.63 -1350.1,871.63 -1300.1,871.63 -1250.1,871.63 -1200.1,871.63 -1150.1,871.63 -1100.1,871.63 831.16,872.76 -194.41,874.33 -1499.76,877.45 749.03,877.14 -1811.97,878.13 -1711.06,877.5 205.59,879.02 -1601.81,879.73 -626.3,881.69 949.98,883.26 -54.41,887.59 -830.67,889.43 1541,889.51 -722.38,891.26 -115.59,890.62 65.59,893.72 1747.3,895.22 -1858.64,896.08 997.25,899.56 144.41,900.84 661.55,901.13 1663.85,901 -1958.24,902.38 -1908.24,902.42 -2008.2,904.39 578.16,904.26 -1541.12,905.55 -915.01,906.38 1046.77,906.47 1096.77,906.98 1146.77,906.98 1196.77,906.98 1246.77,906.98 1296.77,906.98 1346.77,906.98 1396.77,906.98 1446.75,908.18 -1748.56,910.58 784.38,912.49 862.38,911.82 -1637.17,915.09 -2056.75,916.32 -661.66,917.05 4.41,916.76 -255.59,919.99 1790.52,920.34 -194.41,924.33 1576.29,924.92 -757.82,926.53 205.59,929.02 1492.36,928.67 -858.38,931.05 1838.49,934.45 2254.27,933.75 696.9,936.49 1699.94,935.6 -2102.09,937.42 -1791.25,936.61 -54.41,937.59 1888.38,937.73 1938.38,937.73 613.52,939.62 -1576.47,940.91 -115.59,940.62 1988.15,942.6 65.59,943.72 -1672.13,950.83 144.41,950.84 -697.01,952.4 815.16,951.89 -932.42,953.25 -1838.15,953.93 885.76,956.01 2036.04,956.97 1611.65,960.28 -397.99,960.83 397.99,960.83 -1887.39,962.6 1528.29,963.44 -1987.38,964.26 -1937.39,963.55 1741.12,963.96 4.41,966.76 -2141.93,967.63 -786.47,967.51 -255.59,969.99 731.57,972.52 -2036.38,974.21 -194.41,974.33 648.87,974.97 -1611.83,976.26 -875.51,978.03 205.59,979.02 2079.65,981.42 1786.65,984.63 -54.41,987.59 -1702.1,990.85 -729.23,990.64 -115.59,990.62 65.59,993.72 1835.32,996.08 -1350.57,997.02 -1067.73,997.02 835.73,997.47 1646.04,996.57 1563.65,998.79 1885.24,998.91 1935.24,998.91 144.41,1000.84 -941.32,1002.45 -2178.6,1003.38 901.01,1003.63 -2091,1005 1984.92,1004.52 2439.04,1010.28 683.65,1010.9 -1644.1,1014.45 2117.23,1014.4 -800.97,1015.36 756.53,1015.84 4.41,1016.76 -255.59,1019.99 2031.35,1023.07 -194.41,1024.33 -881.16,1027.71 205.59,1029.02 1032.38,1032.38 1315.22,1032.38 1598.05,1035.08 -1723.92,1035.84 -54.41,1037.59 1673.47,1038.37 -741.16,1039.2 2143.24,1038.74 -115.59,1040.62 65.59,1043.72 -2134.76,1047.23 844.99,1046.6 144.41,1050.84 2068,1051 -942.34,1052.44 906.84,1053.29 704.43,1056.38 -1666.97,1058.91 -802.34,1065.34 766.74,1064.79 4.41,1066.76 -1845.55,1067.73 -255.59,1069.99 -194.41,1074.33 1624.53,1077.49 -881.16,1077.71 205.59,1079.02 2099.4,1082.58 -1737.05,1084.08 1693.12,1084.35 -54.41,1087.59 -741.16,1089.2 -115.59,1090.62 65.59,1093.72 845.81,1096.59 144.41,1100.84 -942.34,1102.44 906.98,1103.29 1810.19,1103.09 705.81,1106.36 -1678.74,1107.51 -802.34,1115.34 766.98,1114.79 4.41,1116.76 -255.59,1119.99 -194.41,1124.33 1640.28,1124.94 -881.16,1127.71 205.59,1129.02 1704.03,1133.14 -1741.37,1133.9 -1492,1138.44 -1209.15,1138.44 -54.41,1137.59 -741.16,1139.2 -115.59,1140.62 65.59,1143.72 -474.53,1145.61 474.53,1145.61 845.81,1146.59 144.38,1150.84 -942.34,1152.44 906.98,1153.29 705.81,1156.36 -1680.19,1157.49 -802.34,1165.34 766.98,1164.79 4.41,1166.76 -256.47,1169.99 -195.26,1174.32 1173.8,1173.8 1456.64,1173.8 1644.84,1174.73 -881.16,1177.71 207.63,1178.97 1706.01,1183.11 -1741.37,1183.9 -54.41,1187.59 -741.16,1189.2 -115.59,1190.62 65.59,1193.72 845.81,1196.59 149.36,1200.59 2107.85,1201.41 -942.34,1202.44 906.98,1203.29 705.81,1206.36 -1680.45,1207.49 -1986.97,1209.15 -802.34,1215.34 766.98,1214.79 5.08,1216.76 -267.42,1218.77 -204.22,1223.51 1644.84,1224.73 221.58,1226.99 -881.16,1227.71 1706.01,1233.11 -1745.25,1233.74 -57.07,1237.52 -741.16,1239.2 -119.88,1240.43 70.48,1243.48 2150.27,1243.84 1951.61,1244.51 845.81,1246.59 163.76,1248.48 -942.34,1252.44 906.98,1253.29 705.81,1256.36 -1687.32,1257.02 -291.59,1262.54 -802.34,1265.34 766.98,1264.79 12.64,1266.19 247.9,1269.5 -223.42,1269.68 1648.43,1274.61 -881.16,1277.71 -1350.57,1279.86 -1067.73,1279.86 -1761.64,1280.98 1712.86,1282.64 -68.41,1286.22 2192.7,1286.27 -135.29,1288 -741.16,1289.2 86.66,1290.79 188.2,1292.1 845.81,1296.59 -325.82,1298.99 -942.34,1302.44 906.98,1303.29 -1704.55,1303.95 282.47,1305.63 705.81,1306.36 -252.08,1310.65 29.24,1313.35 -802.34,1315.34 766.98,1314.79 1032.38,1315.22 1315.22,1315.22 -1790.17,1322.04 1661.7,1322.81 -881.16,1327.71 1732.87,1328.46 -551.06,1330.39 220.55,1330.23 551.06,1330.39 -161.46,1330.6 -88.88,1331.84 113.53,1332.96 -361.18,1334.34 -741.16,1339.2 317.82,1340.98 -286.88,1346.55 845.81,1346.59 -2128.39,1350.57 -942.34,1352.44 906.98,1353.29 -1736,1354 705.81,1356.36 -1825.04,1356.94 54.47,1356.52 -802.34,1365.34 766.98,1364.79 255.9,1365.58 -195.79,1366.95 1684.89,1367.11 1763.58,1367.92 148.01,1369.16 -396.53,1369.7 -117.05,1373.15 353.18,1376.34 -881.16,1377.71 -322.23,1381.91 2093.04,1385.93 -741.16,1389.2 1789.69,1392.29 86.9,1394.57 845.81,1396.59 -1781.2,1400.78 291.26,1400.94 1908.52,1400.74 -943.15,1402.43 -231.15,1402.3 906.98,1403.29 1712.86,1403 -431.89,1405.05 183.37,1404.52 705.81,1406.36 -151.61,1409.28 388.53,1411.7 -802.73,1415.34 766.98,1414.79 -357.59,1417.27 -1492,1421.28 -1209.15,1421.28 -885.03,1427.56 122.26,1429.93 326.61,1436.29 1745.85,1436.13 -266.5,1437.66 -742.81,1439.17 -467.24,1440.41 218.72,1439.88 1950.95,1443.17 -186.97,1444.63 423.89,1447.05 846.61,1446.59 -959.48,1449.69 -392.94,1452.62 909.66,1453.22 706.28,1456.36 1173.8,1456.64 1456.64,1456.64 -20,1460 -810.32,1464.76 157.61,1465.28 768.3,1464.77 361.97,1471.65 -301.86,1473.01 -902.63,1474.36 254.08,1475.23 -502.6,1475.76 -222.32,1479.99 459.24,1482.41 1993.37,1485.59 -992.81,1486.96 -753.45,1488.02 -428.3,1487.98 859.07,1495.01 933,1497.44 192.97,1500.64 713.06,1505.9 397.32,1507 -337.22,1508.37 -829.53,1510.92 -537.95,1511.12 289.43,1510.59 779.51,1513.5 -933.24,1513.89 -627.6,1515.16 -257.68,1515.35 627.6,1515.16 494.6,1517.76 -1028.17,1522.31 -463.65,1523.33 968.14,1533 -772.66,1534.19 228.32,1535.99 886.14,1537.05 432.68,1542.36 -372.57,1543.72 324.79,1545.94 -968.59,1549.25 -570.05,1549.45 -859.36,1551.05 -293.03,1550.7 729.29,1553.19 528.02,1554.95 1754.29,1554.97 -1064.07,1557.11 801.88,1558.21 -498.89,1558.8 -1633.42,1562.71 1003.5,1568.35 263.68,1571.35 921.26,1572.63 -799.85,1576.14 467.58,1578.16 -407.93,1579.08 360.14,1581.3 -1105.27,1585.44 -1003.95,1584.61 -328.39,1586.06 -894.49,1586.63 -594.77,1592.92 554.43,1597.41 753.84,1596.75 833.83,1596.67 1796.72,1597.39 1598.06,1598.06 -529.14,1598.61 1040.19,1602.32 -1151.99,1603.27 299.03,1606.7 956.62,1607.99 -1251.59,1609.48 -1201.59,1609.56 -1301.55,1611.5 -834.01,1612.66 -443.22,1614.49 395.5,1616.65 -1041.44,1617.68 496.38,1619.03 -363.74,1621.41 -929.85,1621.98 -1350.06,1623.59 1083.42,1627.45 869.18,1632.03 785.8,1635.19 -611.09,1640.18 1839.15,1639.82 334.39,1642.06 1131.38,1641.56 992.71,1642.59 -1084.13,1643.71 572.2,1644.14 -1395.35,1644.79 -548.69,1644.63 1181.28,1644.84 1231.28,1644.84 -869.37,1648.01 1281.04,1649.71 426.84,1655.61 -469.73,1656.89 -398.89,1656.97 -964.82,1657.72 -220,1660 -20,1660 180,1660 -1131.04,1661.03 1328.93,1664.07 514.76,1665.53 904.54,1667.38 -1180.28,1669.7 -1280.27,1671.37 -1230.27,1670.66 821.17,1670.53 1033.87,1670.98 -1435.16,1675.04 368.88,1678.26 -1329.26,1681.33 -904.72,1683.37 1372.54,1688.53 -618.06,1689.69 1079.38,1691.69 581.48,1693.27 -556.87,1693.96 -994.85,1697.7 -704.14,1699.94 704.14,1699.94 -417.36,1703.43 441.69,1703.35 1128.04,1703.16 -1774.84,1704.13 938.94,1703.67 -478.59,1706.1 856.53,1705.89 1177.96,1706.01 1227.96,1706.01 -1471.49,1710.49 -1382,1711 1277.65,1711.6 521.34,1715.09 -937,1721.56 1410.13,1721.5 381.41,1726.66 1324.1,1730.11 1739.48,1739.48 -618.59,1739.69 890.93,1742.17 -1016.7,1742.67 582.59,1743.26 -557.41,1743.96 966.37,1745.48 1436.13,1745.85 -417.41,1753.43 442.59,1753.34 -1426.93,1753.64 1554.97,1754.29 -478.59,1756.1 1360,1757 521.41,1765.09 -959.87,1766.02 -1138.44,1774.84 381.41,1776.66 917.42,1784.58 -618.59,1789.69 1392.29,1789.69 -1029.9,1790.9 986.02,1791.45 582.59,1793.26 -557.41,1793.96 1597.39,1796.72 -417.41,1803.43 442.59,1803.34 -478.59,1806.1 1103.09,1810.19 -971.63,1814.62 521.41,1815.09 381.41,1826.66 933.17,1832.04 1639.82,1839.15 -618.59,1839.69 996.92,1840.25 -1034.26,1840.71 582.7,1843.26 -557.36,1843.96 -417.41,1853.43 442.59,1853.34 -478.59,1856.1 -220,1860 -20,1860 180,1860 -973.09,1864.6 522.55,1865.08 381.41,1876.66 937.73,1881.83 -780.67,1884.71 780.67,1884.71 -624.65,1889.32 998.91,1890.21 -1034.26,1890.71 589.34,1892.82 -562.81,1893.66 -416.93,1903.43 442.46,1903.34 -478.24,1906.1 1400.74,1908.52 531.94,1914.19 -973.35,1914.6 -1279.86,1916.26 375.49,1926.31 937.73,1931.83 -642.28,1936.1 607.84,1939.27 998.91,1940.21 -1038.09,1940.56 -577.33,1941.5 -395.93,1948.81 1443.17,1950.95 431.04,1952.02 1244.51,1951.61 -465.99,1954.57 549.83,1960.88 -980.21,1964.12 343.78,1964.97 -670.44,1977.42 636.76,1980.06 941.32,1981.7 -360.58,1984.17 -600.04,1986.05 -1054.4,1987.82 1005.75,1989.74 402.31,1992.95 1485.59,1993.37 -436.39,1994.87 308.42,2000.32 576.29,2003.31 -997.44,2011.06 -705.21,2013.36 671.68,2015.84 -325.22,2019.52 -630.95,2025.35 366.96,2028.3 -1082.87,2028.93 -401.03,2030.22 954.58,2029.91 273.07,2035.68 1025.76,2035.56 609.77,2040.44 -739.93,2049.34 706.24,2051.98 -289.87,2054.88 -1421.28,2057.68 -518,2060 -20,2060 482,2060 -666.17,2060.84 -1030,2062.63 -1117.94,2064.04 331.6,2063.66 -365.68,2065.58 -857.21,2069.49 857.21,2069.49 237.8,2071.13 977.78,2074.2 1056.47,2075.02 645.13,2075.8 -768.51,2090.36 -257.15,2092.69 1385.93,2093.04 734.07,2093.52 -700.26,2097.42 296.25,2099.01 1082.58,2099.4 -330.32,2100.93 -1074.1,2107.89 1201.41,2107.85 1006,2110 211.18,2113.45 676.06,2115.08 -787.84,2136.47 -239.18,2139.35 266.92,2139.5 752.97,2139.81 -724.61,2141.09 -301.73,2141.95 1038.74,2143.24 1243.84,2150.27 695.35,2161.21 201.35,2162.47 -798,2189 -237.41,2189.32 262.59,2189.32 761.71,2189.04 -736.26,2189.71 -298.59,2191.85 1286.27,2192.7 701.84,2210.79 201.86,2212.47 -799,2250 -737,2250 -299,2250 -237,2250 201,2250 263,2250 701,2250 763,2250 -933.75,2254.27 933.75,2254.27 -518,2260 -20,2260 482,2260 1047.19,2262.07 1089.61,2304.5 1132.04,2346.93 -1010.28,2439.04 1010.28,2439.04 -518,2460 -20,2460 482,2460
  other v2: 1160.72,-2338.76 1207.38,-2292.09 -1210.21,-2289.26 1099.2,-2277.24 -1256.88,-2242.59 1145.87,-2230.57 -1148.69,-2227.74 1037.68,-2215.72 -1195.36,-2181.07 1084.35,-2169.05 -1087.18,-2166.22 -1133.85,-2119.55 1514.27,-1985.2 1560.94,-1938.53 -1563.77,-1935.7 1452.75,-1923.68 -1610.44,-1889.04 1499.42,-1877.01 -1502.25,-1874.19 1391.23,-1862.17 -1548.92,-1827.52 1437.9,-1815.5 -1440.73,-1812.67 -1487.4,-1766 1867.82,-1631.65 1914.49,-1584.98 -1917.32,-1582.15 1806.3,-1570.13 -1963.99,-1535.48 1852.97,-1523.46 -1855.8,-1520.63 1744.79,-1508.61 -1902.47,-1473.96 1791.45,-1461.94 -1794.28,-1459.11 -1840.95,-1412.45 2221.38,-1278.1 2268.04,-1231.43 -2270.87,-1228.6 2159.86,-1216.58 -2317.54,-1181.93 2206.53,-1169.91 -2209.36,-1167.08 2098.34,-1155.06 -2256.02,-1120.41 2145.01,-1108.39 -2147.84,-1105.56 -2194.51,-1058.89 2300.5,-801 2387.5,-801 2474.5,-801 2300.5,-735 2387.5,-735 2474.5,-735 2300.5,-301 2387.5,-301 2474.5,-301 2300.5,-235 2387.5,-235 2474.5,-235 2300.5,199 2387.5,199 2474.5,199 2300.5,265 2387.5,265 2474.5,265 2300.5,699 2387.5,699 2474.5,699 2300.5,765 2387.5,765 2474.5,765 -2215.72,1037.68 -2169.05,1084.35 -2277.24,1099.2 -2230.57,1145.87 -2338.76,1160.72 -2292.09,1207.38 -1862.17,1391.23 -1815.5,1437.9 -1923.68,1452.75 -1877.01,1499.42 -1985.2,1514.27 -1938.53,1560.94 -1508.61,1744.79 -1461.94,1791.46 -1570.13,1806.3 -1523.46,1852.97 -1631.65,1867.82 -1584.98,1914.49 -1155.06,2098.34 -1108.39,2145.01 -1216.58,2159.86 -1169.91,2206.53 -1278.1,2221.38 -1231.43,2268.04 -801,2300.5 -735,2300.5 265,2300.5 699,2300.5 765,2300.5 -301,2300.5 -235,2300.5 199,2300.5 -801,2387.5 -301,2387.5 -235,2387.5 199,2387.5 765,2387.5 -735,2387.5 265,2387.5 699,2387.5 -801,2474.5 699,2474.5 765,2474.5 -735,2474.5 -301,2474.5 -235,2474.5 199,2474.5 265,2474.5
  other v3: -1830,-317.4 -1852.64,-280 -1807.36,-280 -1830,-242.6 0,-116.92 -37.58,-79.34 37.58,-79.34 -41.76,-41.76 41.76,-41.76 -79.34,-37.58 -116.92,0 116.92,0 -79.34,37.58 79.34,37.58 -41.76,41.76 41.76,41.76 37.58,79.34 0,116.92 -1830,202.6 -1852.64,240 -1807.36,240 -1830,277.4
  other v4: 2262.07,1047.19 2304.5,1089.61 2346.93,1132.04
  other v5: -2350,700
LGCN: C26.2 R33.1 U1.27 | length 2332
  Top Layer w10: U1.27@59.85,101.61 67.51,109.27 ccw(c-24.41,201.19) 105.59,201.19 105.59,228.61 cw(c218.28,228.61) 138.59,308.3 240.42,410.12 cw(c291.63,358.91) 255.42,421.63
  Top Layer w12: 255.42,421.63 cw(c291.63,358.91) 272.88,428.87
  Top Layer w14: 272.88,428.87 cw(c291.63,358.91) 291.63,431.34
  Top Layer w16: 291.63,431.34 316.48,431.34 ccw(c316.48,503.76) 367.7,452.55 806.1,890.95 ccw(c636.4,1060.66) 876.4,1060.66 876.4,1432.22 cw(c1002.63,1432.22) 913.37,1521.48 997.02,1605.13 cw(c1166.73,1435.43) 1166.73,1675.43 1233.29,1675.43 ccw(c1233.29,1889.29) C26.2@1384.52,1738.07
LGCP: C25.2 R29.2 U1.28 | length 2332
  Top Layer w10: U1.28@45.93,115.53 U1.28@52.93,122.52 ; U1.28@52.92,122.52 ccw(c-25.92,201.37) 85.59,201.37 85.59,228.61 cw(c218.28,228.61) 124.45,322.44 226.27,424.26 ccw(c175.06,475.48) 237.78,439.26
  Top Layer w12: 237.78,439.26 ccw(c175.06,475.48) 245.02,456.73
  Top Layer w14: 245.02,456.73 ccw(c175.06,475.48) 247.49,475.48
  Top Layer w16: 247.49,475.48 247.49,500.33 cw(c319.91,500.33) 268.7,551.54 R29.2@286.38,569.22 698.98,981.82 ccw(c608.63,1072.16) 736.4,1072.16 736.4,1443.09 cw(c976.4,1443.09) 806.69,1612.79 898.03,1704.13 ccw(c728.32,1873.83) 968.32,1873.83 968.32,1940.4 cw(c1182.17,1940.4) C25.2@1030.96,2091.62
LGSN: C30.2 R35.1 U1.23 | length 2332
  Top Layer w10: U1.23@115.53,45.93 122.41,52.82 cw(c201.53,-26.3) 201.53,85.59 228.61,85.59 ccw(c228.61,218.28) 322.44,124.45 424.26,226.27 cw(c475.48,175.06) 439.26,237.78
  Top Layer w12: 439.26,237.78 cw(c475.48,175.06) 456.73,245.02
  Top Layer w14: 456.73,245.02 cw(c475.48,175.06) 475.48,247.49
  Top Layer w16: 475.48,247.49 500.33,247.49 ccw(c500.33,319.91) 551.54,268.7 R35.1@569.22,286.38 981.89,699.05 cw(c1072.06,608.87) 1072.06,736.4 1443.09,736.4 ccw(c1443.09,976.4) 1612.79,806.69 1704.13,898.03 cw(c1873.83,728.32) 1873.83,968.32 1940.39,968.32 ccw(c1940.39,1182.19) C30.2@2091.62,1030.96
LGSP: C28.2 R31.2 U1.24 | length 2332
  Top Layer w10: U1.24@101.61,59.85 109.27,67.51 cw(c201.19,-24.41) 201.19,105.59 228.61,105.59 ccw(c228.61,218.28) 308.3,138.59 410.12,240.42 ccw(c358.91,291.63) 421.63,255.42
  Top Layer w12: 421.63,255.42 ccw(c358.91,291.63) 428.87,272.88
  Top Layer w14: 428.87,272.88 ccw(c358.91,291.63) 431.34,291.63
  Top Layer w16: 431.34,291.63 431.34,316.48 cw(c503.76,316.48) 452.55,367.7 890.95,806.1 cw(c1060.66,636.4) 1060.66,876.4 1432.22,876.4 ccw(c1432.22,1002.63) 1521.48,913.37 1605.13,997.02 ccw(c1435.43,1166.73) 1675.43,1166.73 1675.43,1233.28 cw(c1889.3,1233.28) C28.2@1738.07,1384.51
NetC1_1: C1.1 J2.1 | length 238
  Top Layer w16: C1.1@1719.68,-1436.84 J2.1@1887.98,-1605.13
NetC1_2: C1.2 U1.14 | length 2332
  Top Layer w10: U1.14@59.85,-101.61 127.41,-169.17 ccw(c254.56,-42.03) 254.56,-221.84 cw(c254.56,-381.84) 367.7,-268.7 374.77,-275.77 cw(c323.55,-326.98) 386.28,-290.77
  Top Layer w12: 386.28,-290.77 cw(c323.55,-326.98) 393.51,-308.24
  Top Layer w14: 393.51,-308.24 cw(c323.55,-326.98) 395.98,-326.98
  Top Layer w16: 395.98,-326.98 395.98,-351.84 ccw(c468.41,-351.84) 417.19,-403.05 855.6,-841.46 ccw(c1025.3,-671.75) 1025.3,-911.75 1400.96,-911.75 cw(c1400.96,-1028.09) 1483.23,-945.83 1569.78,-1032.38 cw(c1400.07,-1202.08) 1640.07,-1202.08 1640.07,-1268.64 ccw(c1853.94,-1268.64) C1.2@1702.71,-1419.87
NetC2_1: C2.1 J3.1 | length 238
  Top Layer w16: C2.1@2073.24,-1083.29 J3.1@2241.53,-1251.58
NetC2_2: C2.2 U1.15 | length 2332
  Top Layer w10: U1.15@73.77,-87.69 140.79,-154.71 ccw(c254.56,-40.94) 254.56,-201.84 cw(c254.56,-381.84) 381.84,-254.56 388.91,-261.63 ccw(c440.12,-210.42) 403.91,-273.14
  Top Layer w12: 403.91,-273.14 ccw(c440.12,-210.42) 421.38,-280.37
  Top Layer w14: 421.38,-280.37 ccw(c440.12,-210.42) 440.12,-282.84
  Top Layer w16: 440.12,-282.84 464.97,-282.84 cw(c464.97,-355.27) 516.19,-304.06 949.29,-737.16 ccw(c1032.8,-653.65) 1032.8,-771.75 1407.73,-771.75 cw(c1407.73,-1011.75) 1577.44,-842.05 1668.77,-933.38 ccw(c1838.48,-763.68) 1838.48,-1003.68 1905.04,-1003.68 cw(c1905.04,-1217.55) C2.2@2056.27,-1066.32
